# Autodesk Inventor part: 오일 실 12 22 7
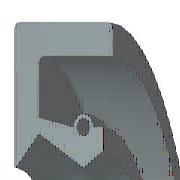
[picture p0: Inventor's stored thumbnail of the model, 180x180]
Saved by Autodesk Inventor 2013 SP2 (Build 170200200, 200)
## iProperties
IsCustomPart: 1
Created: 2012-02
Part Number: 오일 실 12 22 7
Material: 고무
Description: 오일-실
Document SubType Name: Modeling
Standard: KS B 2804
Designer: mduedu
Standards Organization: KS
Language: ko-KR
Size Designation: D - 12 22 7
Categories: <MemberInstance><Categories><Category DisplayName="샤프트 부품" InternalName="7f7aeb1f-a693-4053-b835-cee3144e0d98" Mnemonic="SHFT"><Category DisplayName="실링" Intern
Density: 0.93 g/cm^3
Mass: 1.25383 g
Surface Area: 18.4996 cm^2
Volume: 1.3482 cm^3
Author: mduedu
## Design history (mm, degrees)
revolve "본체" stored, may be unused: angle "d17" = 90 deg
revolve "스프링1" stored, may be unused: angle "d18" = 90 deg
body "Solid1"
sketch "스케치1"
  geometry: L1 (0, 11)-(7, 11); L2 (7, 9.25)-(1.75, 9.25); L3 (1.75, 7.75)-(4.9, 6); L4 (4.9, 6)-(0, 6); L5 (0, 0)-(9.586, 0) reference; L6 (4.9, 6)-(6.3, 6.875); L7 (0, 18)-(0, -3) reference; L8 (-1.941, 0)-(11.507, 0) reference; L9 (4.2, 8.1)-(1.75, 8.59); L10 (1.75, 8.59)-(1.75, 9.25); L11 (0, 11)-(0, 6.088); L12 (4.9, 6)-(0, 6); L13 (1.75, 7.75)-(0.152, 6.028); L14 (7, 11)-(7, 9.25); L15 (5.6, 8.1)-(6.3, 8.1); L16 (6.3, 8.1)-(6.3, 6.875); C1 r 0.455 at (4.9, 8.1); A1 r 0.7 centre (4.9, 8.1) between (5.6, 8.1) and (4.2, 8.1); A2 r 0.088 centre (0.088, 6.088) between (0, 6.088) and (0.152, 6.028); 1 further point
  constraints: 28 end point, 5 horizontal alignment, 5 point on line, 4 point on circle, 4 vertical alignment, 3 centre point, 3 tangent, 2 collinear, 2 horizontal, 2 perpendicular, 1 coincident, 1 parallel
  dimensions: "d0" = 22 diameter of L1 L5 (= SD2); "d1" = 1.75 distance of L1.end L2.start (= SD); "d2" = 0.91 diameter of C1 (= SPDI); "d3" = 1.4 diameter of A1 (= SPDA); "d4" = 12 diameter of L3.end L5 (= NND); "d5" = 15.5 diameter of L3.start L5 (= TKDM); "d7" = 17.18 diameter of L9.end L5 (= TKDM + 0.24 x SWDT); "d8" = 1.75 distance between parallel lines of L11 L10 (= SD); "d9" = 4.9 distance from line of L11 C1.centre (= SPDST); "d10" = 16.2 diameter of C1.centre L5 (= HLDM); "d11" = 0.0875 radius of A2 (= 0.25 x LAB); "d12" = 6.3 distance between parallel lines of L11 L16 (= SDI); "d13" = 13.75 diameter of L6.end L5 (= ABDM); "d14" = 7 distance from line of L11 L1.end (= SWDT)
fillet "모깎기1" dims "d6" = 0.3 (= RR)
other parameters: "SD2" = 22 [user parameter; used in 1 equation term], "SWDT" = 7 [user parameter; used in 2 equation terms], "RR" = 0.3 [user parameter; used in 1 equation term], "SD" = 1.75 [user parameter; used in 2 equation terms], "NND" = 12 [user parameter; used in 1 equation term], "SPDA" = 1.4 [user parameter; used in 1 equation term], "SPDI" = 0.91 [user parameter; used in 1 equation term], "TKDM" = 15.5 [user parameter; used in 2 equation terms], "HLDM" = 16.2 [user parameter; used in 1 equation term], "ABDM" = 13.75 [user parameter; used in 1 equation term], "SDI" = 6.3 [user parameter; used in 1 equation term], "SPDST" = 4.9 [user parameter; used in 1 equation term], "LAB" = 0.35 [user parameter; used in 1 equation term], "d15" = 0, "d16" = 0, "d19" = 0
